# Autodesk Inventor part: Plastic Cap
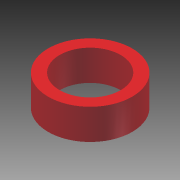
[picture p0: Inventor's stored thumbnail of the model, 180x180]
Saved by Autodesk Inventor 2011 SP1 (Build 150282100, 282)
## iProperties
Created: 2011-10
Part Number: Plastic Cap
Document SubType Name: Modeling
Designer: sdarley
Density: 1 g/cm^3
Author: sdarley
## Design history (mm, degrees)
sketch "Sketch1"
  geometry: C1 r 5.5 at (0, 0); C2 r 4 at (0, 0); 1 further point
  constraints: 2 centre point, 2 coincident
  dimensions: "d0" = 11 diameter of C1; "d1" = 8 diameter of C2
extrude "Extrusion1" new body sketch "Sketch1" distance "d2" = 4; taper "d3" = 0 deg
body "Solid1"
